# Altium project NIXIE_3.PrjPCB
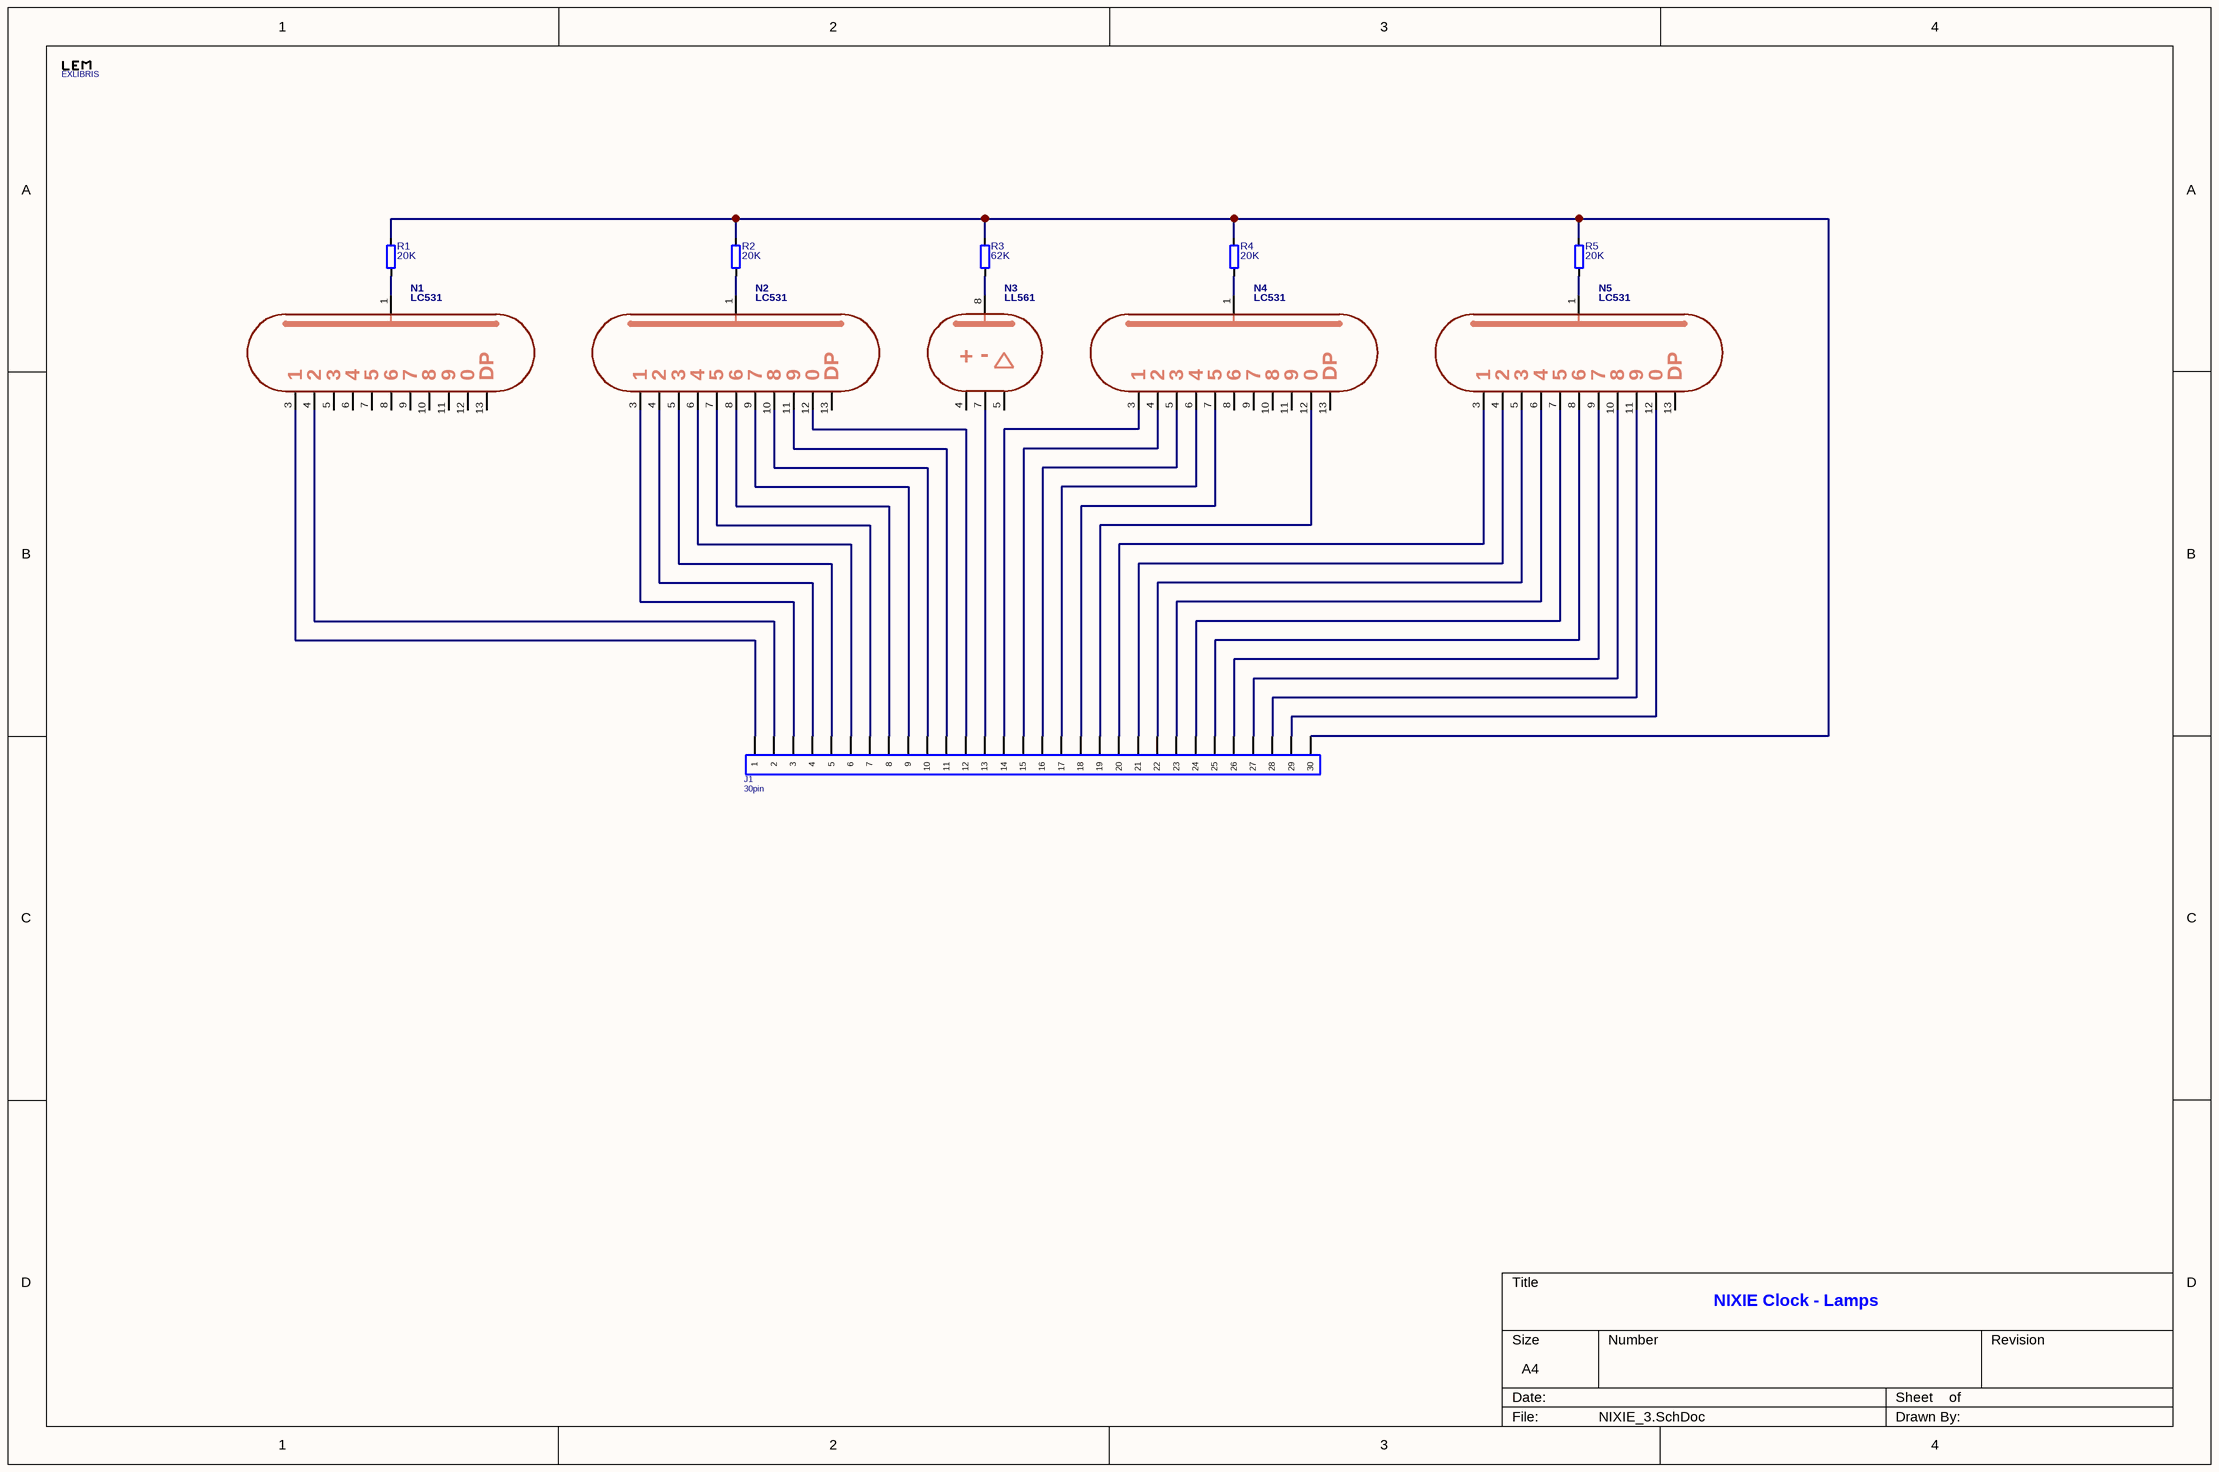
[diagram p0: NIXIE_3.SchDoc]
1 sheet, 12 parts. Net scope: global (net labels, ports and power ports of the same name join across sheets).
Board file: NIXIE_3.PcbDoc

## Sheet NIXIE_3.SchDoc
size A4; PageSetup: Record=PageOptions¦CenterHorizontal=True¦CenterVertical=True¦PrintScale=0.34¦XCorrection=1.00¦YCorrection=1.00¦PrintKind=0¦BorderSize=5000000¦LeftOffset=0¦BottomOffset=0¦Orientation=2¦PaperLength=1000¦PaperWidth=1000¦Scale=100¦PaperSource=7¦PrintQuality=-3¦MediaType=1¦DitherType=10¦PrintScaleMode=1¦PaperKind=A4¦PaperIndex=9

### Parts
EXLIBRIS  EXLIBRIS  [EXLBS_2]
J1  30pin  [SIL30]
N1  LC531  [Nixie LC531]
N2  LC531  [Nixie LC531]
N3  LL561  [NIXIE LL561]
N4  LC531  [Nixie LC531]
N5  LC531  [Nixie LC531]
R1  20K  [SMD_R_0805]
R2  20K  [SMD_R_0805]
R3  62K  [SMD_R_0805]
R4  20K  [SMD_R_0805]
R5  20K  [SMD_R_0805]

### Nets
NetJ1_1: J1.1 N1.3(1)
NetJ1_2: J1.2 N1.4(2)
NetJ1_3: J1.3 N2.3(1)
NetJ1_4: J1.4 N2.4(2)
NetJ1_5: J1.5 N2.5(3)
NetJ1_6: J1.6 N2.6(4)
NetJ1_7: J1.7 N2.7(5)
NetJ1_8: J1.8 N2.8(6)
NetJ1_9: J1.9 N2.9(7)
NetJ1_10: J1.10 N2.10(8)
NetJ1_11: J1.11 N2.11(9)
NetJ1_12: J1.12 N2.12(0)
NetJ1_13: J1.13 N3.7(-)
NetJ1_14: J1.14 N4.3(1)
NetJ1_15: J1.15 N4.4(2)
NetJ1_16: J1.16 N4.5(3)
NetJ1_17: J1.17 N4.6(4)
NetJ1_18: J1.18 N4.7(5)
NetJ1_19: J1.19 N4.12(0)
NetJ1_20: J1.20 N5.3(1)
NetJ1_21: J1.21 N5.4(2)
NetJ1_22: J1.22 N5.5(3)
NetJ1_23: J1.23 N5.6(4)
NetJ1_24: J1.24 N5.7(5)
NetJ1_25: J1.25 N5.8(6)
NetJ1_26: J1.26 N5.9(7)
NetJ1_27: J1.27 N5.10(8)
NetJ1_28: J1.28 N5.11(9)
NetJ1_29: J1.29 N5.12(0)
NetJ1_30: J1.30 R1.2 R2.2 R3.2 R4.2 R5.2
NetN1_1: N1.1(A) R1.1
NetN2_1: N2.1(A) R2.1
NetN3_8: N3.8(A) R3.1
NetN4_1: N4.1(A) R4.1
NetN5_1: N5.1(A) R5.1

Not connected (* = marked no-connect by the designer): N1 5(3) 6(4) 7(5) 8(6) 9(7) 10(8) 11(9) 12(0) 13(DP); N2 13(DP); N3 4(+) 5(DELTA); N4 8(6) 9(7) 10(8) 11(9) 13(DP); N5 13(DP)

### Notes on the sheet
- NIXIE Clock - Lamps

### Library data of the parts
EXLIBRIS = EXLBR
J1 = CON 30pin
N1 N2 N4 N5 = NIXIE LC531: Lampa Numeryczna Nixie
N3 = NIXIE LL561: SIGN NEON LAMP
R1-R5 = R: Resistor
